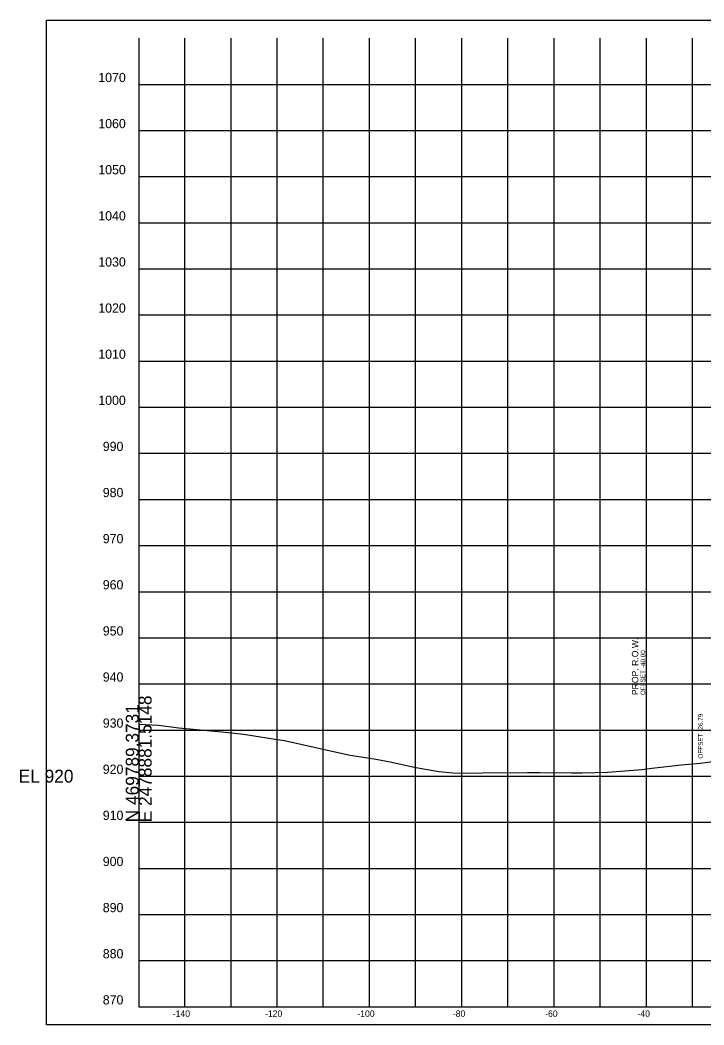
# Model space of a CAD drawing. Extents: x -26 to 2478923, y -10 to 469990.
# Drawn here: x -25.7 to 122.5, y 2446.1 to 2663.9 of the extents above; entities that cross this region are included whole.
import ezdxf

# ---------------------------------------------------------------- set-up
doc = ezdxf.new("R2010")
doc.units = 0
for name, color, linetype in [('DESIGN - ROW - Right-of-Way and Easement Labels', 7, 'Continuous'), ('DESIGN - ROW - Right-of-Way Linework', 7, 'Continuous'), ('DESIGN - SHEET - Corner Text', 7, 'Continuous'), ('DESIGN - SHEET - Light Grid', 7, 'Continuous'), ('DESIGN - SHEET - Linework', 7, 'Continuous'), ('DESIGN - SHEET - Plot Shape', 7, 'Continuous'), ('DESIGN - TYPICAL - Slope Tie Text', 7, 'Continuous'), ('SURVEY - GROUND - Top of Ground', 7, 'Continuous')]:
    doc.layers.add(name, color=color, linetype=linetype)

msp = doc.modelspace()

# ---------------------------------------------------------------- linework, layer by layer
at = {"layer": 'DESIGN - ROW - Right-of-Way Linework'}
msp.add_line((110, 2501.56), (110, 2533.56), dxfattribs=at)
at = {"layer": 'DESIGN - SHEET - Light Grid'}
msp.add_line((0, 2500), (150, 2500), dxfattribs=at)
at = {"layer": 'DESIGN - SHEET - Linework'}
for p, q in [((10, 2450), (10, 2660)), ((10, 2450), (10, 2660)), ((10, 2450), (10, 2660)), ((10, 2450), (10, 2660)), ((20, 2450), (20, 2660)), ((20, 2450), (20, 2660)), ((20, 2450), (20, 2660)), ((20, 2450), (20, 2660)), ((30, 2450), (30, 2660)), ((30, 2450), (30, 2660)), ((30, 2450), (30, 2660)), ((30, 2450), (30, 2660)), ((40, 2450), (40, 2660)), ((40, 2450), (40, 2660)), ((40, 2450), (40, 2660)), ((40, 2450), (40, 2660)), ((50, 2450), (50, 2660)), ((50, 2450), (50, 2660)), ((50, 2450), (50, 2660)), ((50, 2450), (50, 2660)), ((60, 2450), (60, 2660)), ((60, 2450), (60, 2660)), ((60, 2450), (60, 2660)), ((60, 2450), (60, 2660)), ((70, 2450), (70, 2660)), ((70, 2450), (70, 2660)), ((70, 2450), (70, 2660)), ((70, 2450), (70, 2660)), ((80, 2450), (80, 2660)), ((80, 2450), (80, 2660)), ((80, 2450), (80, 2660)), ((80, 2450), (80, 2660)), ((90, 2450), (90, 2660)), ((90, 2450), (90, 2660)), ((90, 2450), (90, 2660)), ((90, 2450), (90, 2660)), ((100, 2450), (100, 2660)), ((100, 2450), (100, 2660)), ((100, 2450), (100, 2660)), ((100, 2450), (100, 2660)), ((110, 2450), (110, 2660)), ((110, 2450), (110, 2660)), ((110, 2450), (110, 2660)), ((110, 2450), (110, 2660)), ((120, 2450), (120, 2660)), ((120, 2450), (120, 2660)), ((120, 2450), (120, 2660)), ((120, 2450), (120, 2660)), ((0, 2650), (300, 2650)), ((0, 2650), (300, 2650)), ((0, 2650), (300, 2650)), ((0, 2650), (300, 2650)), ((0, 2640), (300, 2640)), ((0, 2640), (300, 2640)), ((0, 2640), (300, 2640)), ((0, 2640), (300, 2640)), ((0, 2630), (300, 2630)), ((0, 2630), (300, 2630)), ((0, 2630), (300, 2630)), ((0, 2630), (300, 2630)), ((0, 2620), (300, 2620)), ((0, 2620), (300, 2620)), ((0, 2620), (300, 2620)), ((0, 2620), (300, 2620)), ((0, 2610), (300, 2610)), ((0, 2610), (300, 2610)), ((0, 2610), (300, 2610)), ((0, 2610), (300, 2610)), ((0, 2600), (300, 2600)), ((0, 2600), (300, 2600)), ((0, 2600), (300, 2600)), ((0, 2600), (300, 2600)), ((0, 2590), (300, 2590)), ((0, 2590), (300, 2590)), ((0, 2590), (300, 2590)), ((0, 2590), (300, 2590)), ((0, 2580), (300, 2580)), ((0, 2580), (300, 2580)), ((0, 2580), (300, 2580)), ((0, 2580), (300, 2580)), ((0, 2570), (300, 2570)), ((0, 2570), (300, 2570)), ((0, 2570), (300, 2570)), ((0, 2570), (300, 2570)), ((0, 2560), (300, 2560)), ((0, 2560), (300, 2560)), ((0, 2560), (300, 2560)), ((0, 2560), (300, 2560)), ((0, 2550), (300, 2550)), ((0, 2550), (300, 2550)), ((0, 2550), (300, 2550)), ((0, 2550), (300, 2550)), ((0, 2540), (300, 2540)), ((0, 2540), (300, 2540)), ((0, 2540), (300, 2540)), ((0, 2540), (300, 2540)), ((0, 2530), (300, 2530)), ((0, 2530), (300, 2530)), ((0, 2530), (300, 2530)), ((0, 2530), (300, 2530)), ((0, 2520), (300, 2520)), ((0, 2520), (300, 2520)), ((0, 2520), (300, 2520)), ((0, 2520), (300, 2520)), ((0, 2510), (300, 2510)), ((0, 2510), (300, 2510)), ((0, 2510), (300, 2510)), ((0, 2510), (300, 2510)), ((0, 2500), (300, 2500)), ((0, 2500), (300, 2500)), ((0, 2500), (300, 2500)), ((0, 2500), (300, 2500)), ((0, 2490), (300, 2490)), ((0, 2490), (300, 2490)), ((0, 2490), (300, 2490)), ((0, 2490), (300, 2490)), ((0, 2480), (300, 2480)), ((0, 2480), (300, 2480)), ((0, 2480), (300, 2480)), ((0, 2480), (300, 2480)), ((0, 2470), (300, 2470)), ((0, 2470), (300, 2470)), ((0, 2470), (300, 2470)), ((0, 2470), (300, 2470)), ((0, 2460), (300, 2460)), ((0, 2460), (300, 2460)), ((0, 2460), (300, 2460)), ((0, 2460), (300, 2460))]:
    msp.add_line(p, q, dxfattribs=at)
msp.add_lwpolyline([(0, 2660), (0, 2450), (300, 2450), (300, 2660)], dxfattribs=at)
msp.add_lwpolyline([(0, 2660), (0, 2450), (300, 2450), (300, 2660)], dxfattribs=at)
msp.add_lwpolyline([(0, 2660), (0, 2450), (300, 2450), (300, 2660)], dxfattribs=at)
msp.add_lwpolyline([(0, 2660), (0, 2450), (300, 2450), (300, 2660)], dxfattribs=at)
at = {"layer": 'DESIGN - SHEET - Plot Shape'}
msp.add_lwpolyline([(-20, 2663.94), (320, 2663.94), (320, 2446.06), (-20, 2446.06)], close=True, dxfattribs=at)
msp.add_lwpolyline([(-20, 2663.94), (320, 2663.94), (320, 2446.06), (-20, 2446.06)], close=True, dxfattribs=at)
msp.add_lwpolyline([(-20, 2663.94), (320, 2663.94), (320, 2446.06), (-20, 2446.06)], close=True, dxfattribs=at)
msp.add_lwpolyline([(-20, 2663.94), (320, 2663.94), (320, 2446.06), (-20, 2446.06)], close=True, dxfattribs=at)
at = {"layer": 'SURVEY - GROUND - Top of Ground'}
msp.add_lwpolyline([(0, 2511.24), (4.32, 2511.07), (8.72, 2510.48), (20.26, 2509.42), (23.22, 2509.04), (29.58, 2508.01), (31.6, 2507.7), (41.58, 2505.5), (45.78, 2504.56), (50.99, 2503.78), (54.84, 2503.05), (59.65, 2501.98), (65.06, 2500.99), (68.09, 2500.72), (70.78, 2500.64), (74.49, 2500.74), (84.24, 2500.78), (86.89, 2500.8), (93.8, 2500.74), (94.96, 2500.75), (96.11, 2500.75), (101.6, 2500.85), (109.11, 2501.45), (111.18, 2501.71), (117.63, 2502.44), (121.68, 2502.85), (130.98, 2504.03)], dxfattribs=at)

# ---------------------------------------------------------------- texts
at = {"layer": 'DESIGN - ROW - Right-of-Way and Easement Labels'}
for s, height, p in [('PROP. R.O.W.', 1.4, (108.25, 2517.56)), ('OFFSET -40.00', 1, (109.75, 2517.56))]:
    msp.add_text(s, height=height, rotation=90, dxfattribs=at).set_placement(p)
at = {"layer": 'DESIGN - SHEET - Corner Text'}
for s, height, p in [('1070', 2, (-8.75, 2650.5)), ('1070', 2, (-8.75, 2650.5)), ('1070', 2, (-8.75, 2650.5)), ('1070', 2, (-8.75, 2650.5)), ('1060', 2, (-8.75, 2640.5)), ('1060', 2, (-8.75, 2640.5)), ('1060', 2, (-8.75, 2640.5)), ('1060', 2, (-8.75, 2640.5)), ('1050', 2, (-8.75, 2630.5)), ('1050', 2, (-8.75, 2630.5)), ('1050', 2, (-8.75, 2630.5)), ('1050', 2, (-8.75, 2630.5)), ('1040', 2, (-8.75, 2620.5)), ('1040', 2, (-8.75, 2620.5)), ('1040', 2, (-8.75, 2620.5)), ('1040', 2, (-8.75, 2620.5)), ('1030', 2, (-8.75, 2610.5)), ('1030', 2, (-8.75, 2610.5)), ('1030', 2, (-8.75, 2610.5)), ('1030', 2, (-8.75, 2610.5)), ('1020', 2, (-8.75, 2600.5)), ('1020', 2, (-8.75, 2600.5)), ('1020', 2, (-8.75, 2600.5)), ('1020', 2, (-8.75, 2600.5)), ('1010', 2, (-8.75, 2590.5)), ('1010', 2, (-8.75, 2590.5)), ('1010', 2, (-8.75, 2590.5)), ('1010', 2, (-8.75, 2590.5)), ('1000', 2, (-8.75, 2580.5)), ('1000', 2, (-8.75, 2580.5)), ('1000', 2, (-8.75, 2580.5)), ('1000', 2, (-8.75, 2580.5)), ('990', 2, (-7.78, 2570.5)), ('990', 2, (-7.78, 2570.5)), ('990', 2, (-7.78, 2570.5)), ('990', 2, (-7.78, 2570.5)), ('980', 2, (-7.78, 2560.5)), ('980', 2, (-7.78, 2560.5)), ('980', 2, (-7.78, 2560.5)), ('980', 2, (-7.78, 2560.5)), ('970', 2, (-7.78, 2550.5)), ('970', 2, (-7.78, 2550.5)), ('970', 2, (-7.78, 2550.5)), ('970', 2, (-7.78, 2550.5)), ('960', 2, (-7.78, 2540.5)), ('960', 2, (-7.78, 2540.5)), ('960', 2, (-7.78, 2540.5)), ('960', 2, (-7.78, 2540.5)), ('950', 2, (-7.78, 2530.5)), ('950', 2, (-7.78, 2530.5)), ('950', 2, (-7.78, 2530.5)), ('950', 2, (-7.78, 2530.5)), ('940', 2, (-7.78, 2520.5)), ('940', 2, (-7.78, 2520.5)), ('940', 2, (-7.78, 2520.5)), ('940', 2, (-7.78, 2520.5)), ('930', 2, (-7.78, 2510.5)), ('930', 2, (-7.78, 2510.5)), ('930', 2, (-7.78, 2510.5)), ('930', 2, (-7.78, 2510.5)), ('920', 2, (-7.78, 2500.5)), ('920', 2, (-7.78, 2500.5)), ('920', 2, (-7.78, 2500.5)), ('920', 2, (-7.78, 2500.5)), ('910', 2, (-7.78, 2490.5)), ('910', 2, (-7.78, 2490.5)), ('910', 2, (-7.78, 2490.5)), ('910', 2, (-7.78, 2490.5)), ('900', 2, (-7.78, 2480.5)), ('900', 2, (-7.78, 2480.5)), ('900', 2, (-7.78, 2480.5)), ('900', 2, (-7.78, 2480.5)), ('890', 2, (-7.78, 2470.5)), ('890', 2, (-7.78, 2470.5)), ('890', 2, (-7.78, 2470.5)), ('890', 2, (-7.78, 2470.5)), ('880', 2, (-7.78, 2460.5)), ('880', 2, (-7.78, 2460.5)), ('880', 2, (-7.78, 2460.5)), ('880', 2, (-7.78, 2460.5)), ('870', 2, (-7.78, 2450.5)), ('870', 2, (-7.78, 2450.5)), ('870', 2, (-7.78, 2450.5)), ('870', 2, (-7.78, 2450.5)), ('-140', 1.4, (7.37, 2447.8)), ('-140', 1.4, (7.37, 2447.8)), ('-140', 1.4, (7.37, 2447.8)), ('-140', 1.4, (7.37, 2447.8)), ('-120', 1.4, (27.37, 2447.8)), ('-120', 1.4, (27.37, 2447.8)), ('-120', 1.4, (27.37, 2447.8)), ('-120', 1.4, (27.37, 2447.8)), ('-100', 1.4, (47.37, 2447.8)), ('-100', 1.4, (47.37, 2447.8)), ('-100', 1.4, (47.37, 2447.8)), ('-100', 1.4, (47.37, 2447.8)), ('-80', 1.4, (68.06, 2447.8)), ('-80', 1.4, (68.06, 2447.8)), ('-80', 1.4, (68.06, 2447.8)), ('-80', 1.4, (68.06, 2447.8)), ('-60', 1.4, (88.06, 2447.8)), ('-60', 1.4, (88.06, 2447.8)), ('-60', 1.4, (88.06, 2447.8)), ('-60', 1.4, (88.06, 2447.8)), ('-40', 1.4, (108.06, 2447.8)), ('-40', 1.4, (108.06, 2447.8)), ('-40', 1.4, (108.06, 2447.8)), ('-40', 1.4, (108.06, 2447.8))]:
    msp.add_text(s, height=height, dxfattribs=at).set_placement(p)
at = {"layer": 'DESIGN - SHEET - Light Grid'}
for s, p in [('E 2478881.5148', (2.8, 2490)), ('N 469789.3731', (0, 2490))]:
    msp.add_text(s, height=2.8, rotation=90, dxfattribs=at).set_placement(p)
msp.add_text('EL 920', height=2.8, dxfattribs=at).set_placement((-26, 2498.6))
at = {"layer": 'DESIGN - TYPICAL - Slope Tie Text'}
msp.add_text('OFFSET -26.79', height=1, rotation=90, dxfattribs=at).set_placement((122.21, 2503.8))

doc.saveas('drawing.dxf')
